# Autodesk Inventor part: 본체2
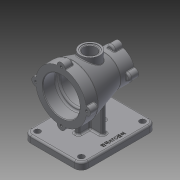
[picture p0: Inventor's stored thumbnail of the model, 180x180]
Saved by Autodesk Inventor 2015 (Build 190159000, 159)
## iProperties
Created: 2020-12
Part Number: 본체2
Material: 일반
Document SubType Name: Modeling
Designer: Lineart
Density: 1 g/cm^3
Appearance: 기본값
Author: Lineart
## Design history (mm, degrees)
sketch "스케치1"
  geometry: L1 (-50, 0)-(50, 0); L2 (-50, 0)-(-50, 44); L3 (-50, 44)-(-30, 44); L4 (-30, 44)-(25.698, 27.5); L5 (25.698, 27.5)-(50, 27.5); L6 (50, 27.5)-(50, 0); 2 further points
  constraints: 12 end point, 2 perpendicular, 1 coincident, 1 horizontal, 1 midpoint, 1 parallel, 1 vertical
  dimensions: "d1" = 88 diameter of L3 L1; "d2" = 55 diameter of L5 L1; "d4" = 100 distance between parallel lines of L6 L2; "d5" = 20 distance from line of L3.end L2; "d6" = 55.69798 horizontal distance of L3.end L4.end
revolve "회전1" sketch "스케치1" stored, may be unused: angle "d7" = 90 deg
node "작업 평면1"
node "작업 평면2"
sketch "스케치3"
  geometry: L1 (-65, -50)-(65, -50); L2 (65, -50)-(65, 50); L3 (65, 50)-(-65, 50); L4 (-65, 50)-(-65, -50); L5 (-65, -50)-(65, 50); L6 (65, -50)-(-65, 50); 1 further point
  constraints: 12 end point, 2 midpoint, 2 parallel, 1 horizontal, 1 perpendicular
  dimensions: "d9" = 130 distance of L3.end L2.end; "d10" = 100 distance of L2.end L1.end
extrude "돌출1" join sketch "스케치3" distance "d11" = 12; taper "d12" = 0 deg
sketch "스케치5"
  geometry: L1 (0, -4)-(0, 4); L2 (24, 0)-(-24, 0); L3 (-65, -50)-(-65, 50) reference; L4 (65, -50)-(-65, -50) reference; L5 (24, -4)-(24, 4); L6 (-24, -4)-(-24, 4); L7 (24, -4)-(-24, -4); L8 (24, 4)-(-24, 4); 1 further point
  constraints: 12 end point, 4 midpoint, 4 parallel
  dimensions: "d15" = 65 distance between parallel lines of L3 L1; "d16" = 50 distance between parallel lines of L2 L4; "d17" = 24 distance between parallel lines of L1 L5; "d18" = 24 distance between parallel lines of L1 L6; "d19" = 4 distance between parallel lines of L2 L7; "d20" = 4 distance between parallel lines of L2 L8
extrude "돌출2" join sketch "스케치5" distance "d21" = 67.5; taper "d22" = 0 deg
node "작업 평면4"
sketch "스케치6"
  geometry: L1 (-62.176, 4)-(12, 4); L2 (-62.176, -21)-(12, -21); L3 (-62.176, 29)-(12, 29); L4 (12, -46)-(12, 54) reference; L5 (-62.176, -21)-(-62.176, 29); L6 (12, -21)-(12, 29); 1 further point
  constraints: 10 end point, 2 midpoint, 2 parallel, 2 point on line, 1 collinear, 1 horizontal, 1 vertical
  dimensions: "d23" = 25 distance between parallel lines of L1 L2; "d24" = 25 distance between parallel lines of L1 L3; "d25" = 50 distance of L3.end L2.end (derived); "d26" = 74.17552 distance between parallel lines of L4 L5; "d27" = 25 distance from line of L4.end L3
extrude "돌출3" join sketch "스케치6" stored distance "d28" = 8; taper "d29" = 0 deg
sketch "스케치7"
  geometry: L1 (50, 0)-(-50, 0); L2 (50, 44)-(50, -44) reference; L3 (50, 0)-(50, -32); L4 (50, -32)-(30, -32); L5 (27, -29)-(27, -29); L6 (24, -26)-(-17, -26); L7 (-20, -23)-(-20, -23); L8 (-50, 27.5)-(-50, -27.5) reference; L9 (-23, -20)-(-50, -20); L10 (-50, -20)-(-50, 0); A1 r 3 centre (30, -29) between (27, -29) and (30, -32); A2 r 3 centre (24, -29) between (27, -29) and (24, -26); A3 r 3 centre (-17, -23) between (-20, -23) and (-17, -26); A4 r 3 centre (-23, -23) between (-20, -23) and (-23, -20); 1 further point
  constraints: 16 end point, 8 point on circle, 8 tangent, 4 centre point, 4 perpendicular, 3 equal radius, 2 horizontal, 2 midpoint, 2 point on line
  dimensions: "d30" = 64 diameter of L4 L1; "d31" = 52 diameter of L6 L1; "d33" = 23 distance between parallel lines of L5 L2; "d34" = 47 distance between parallel lines of L7 L5; "d36" = 40 diameter of L9 L1; "d37" = 30 distance between parallel lines of L8 L7 (derived); "d38" = 3 radius of A1
revolve "회전2" sketch "스케치7" stored, may be unused: angle "d39" = 90 deg
sketch "스케치8"
  geometry: C1 r 7 at (-44, 0); C2 r 7 at (0, -44); C3 r 7 at (44, 0); C4 r 7 at (0, 44); A1 r 44 centre (0, 0) between (-44, 0) and (0, 44) reference; 3 further points
  constraints: 4 centre point, 4 coincident, 4 point on circle, 2 horizontal alignment, 2 vertical alignment
  dimensions: "d40" = 7 radius of C1; "d41" = 7 radius of C2; "d42" = 7 radius of C3; "d45" = 7 radius of C4
extrude "돌출4" join sketch "스케치8" distance "d46" = 15; taper "d47" = 0 deg
sketch "스케치9"
  geometry: C1 r 7 at (27.5, 0); C2 r 7 at (0, 27.5); C3 r 7 at (-27.5, 0); C4 r 7 at (0, -27.5); A1 r 27.5 centre (0, 0) between (27.5, 0) and (0, 27.5) reference; A2 r 27.5 centre (0, 0) between (27.5, 0) and (0, 27.5) reference; 3 further points
  constraints: 8 point on circle, 4 centre point, 4 coincident, 2 horizontal alignment, 2 vertical alignment
  dimensions: "d48" = 7 radius of C1; "d49" = 7 radius of C2; "d50" = 7 radius of C3; "d51" = 7 radius of C4
extrude "돌출5" join sketch "스케치9" distance "d52" = 15; taper "d53" = 0 deg
hole "구멍1" diameter "d56" = 4.134; stored, may be unused: countersink angle "d60" = 90 deg, drill point angle "d62" = 118 deg; dims "d54" = 10, "d55" = 10, "d57" = 9, "d58" = 4, "d59" = 2, "d61" = 11
hole "구멍2" diameter "d65" = 4.134; stored, may be unused: countersink angle "d69" = 90 deg, drill point angle "d71" = 118 deg; dims "d63" = 10, "d64" = 10, "d66" = 9, "d67" = 4, "d68" = 2, "d70" = 11
hole "구멍3" diameter "d74" = 4.134; stored, may be unused: countersink angle "d78" = 90 deg, drill point angle "d80" = 118 deg; dims "d72" = 10, "d73" = 10, "d75" = 9, "d76" = 4, "d77" = 2, "d79" = 11
hole "구멍4" diameter "d83" = 4.134; stored, may be unused: countersink angle "d87" = 90 deg, drill point angle "d89" = 118 deg; dims "d81" = 10, "d82" = 10, "d84" = 9, "d85" = 4, "d86" = 2, "d88" = 11
hole "구멍5" diameter "d92" = 4.134; stored, may be unused: countersink angle "d96" = 90 deg, drill point angle "d98" = 118 deg; dims "d90" = 10, "d91" = 10, "d93" = 9, "d94" = 4, "d95" = 2, "d97" = 11
hole "구멍6" diameter "d101" = 4.134; stored, may be unused: countersink angle "d105" = 90 deg, drill point angle "d107" = 118 deg; dims "d99" = 10, "d100" = 10, "d102" = 9, "d103" = 4, "d104" = 2, "d106" = 11
hole "구멍7" diameter "d110" = 4.134; stored, may be unused: countersink angle "d114" = 90 deg, drill point angle "d116" = 118 deg; dims "d108" = 10, "d109" = 10, "d111" = 9, "d112" = 4, "d113" = 2, "d115" = 11
hole "구멍8" diameter "d119" = 4.134; stored, may be unused: countersink angle "d123" = 90 deg, drill point angle "d125" = 118 deg; dims "d117" = 10, "d118" = 10, "d120" = 9, "d121" = 4, "d122" = 2, "d124" = 11
fillet "모깎기1" dims "d126" = 12
fillet "모깎기2" dims "d127" = 3
sketch "스케치11"
  geometry: C1 r 5 at (53, -38); C2 r 5 at (53, 38); C3 r 5 at (-53, 38); C4 r 5 at (-53, -38); A1 r 12 centre (53, -38) between (53, -50) and (65, -38) reference; A2 r 12 centre (53, 38) between (65, 38) and (53, 50) reference; A3 r 12 centre (-53, 38) between (-53, 50) and (-65, 38) reference; A4 r 12 centre (-53, -38) between (-65, -38) and (-53, -50) reference; 1 further point
  constraints: 4 centre point, 4 coincident
  dimensions: "d128" = 10 diameter of C1; "d129" = 10 diameter of C2; "d130" = 10 diameter of C3; "d131" = 10 diameter of C4
extrude "돌출6" cut sketch "스케치11" stored distance "d132" = 15; taper "d133" = 0 deg
fillet "모깎기3" dims "d134" = 3
fillet "모깎기4" dims "d135" = 3
fillet "모깎기5" dims "d136" = 3
fillet "모깎기6" dims "d137" = 3
node "작업 평면5"
sketch "스케치13"
  geometry: C1 r 17 at (0, 0); 1 further point
  constraints: 1 centre point, 1 coincident
  dimensions: "d139" = 34 diameter of C1
extrude "돌출7" join sketch "스케치13" distance "d140" = 18.25; taper "d141" = 0 deg
sketch "스케치14"
  geometry: C1 r 14 at (0, 0); 1 further point
  constraints: 1 centre point, 1 coincident
  dimensions: "d142" = 28 diameter of C1
extrude "돌출8" cut sketch "스케치14" distance "d143" = 1; taper "d144" = 0 deg
sketch "스케치15"
  geometry: C1 r 11 at (0, 0); 1 further point
  constraints: 1 centre point, 1 coincident
  dimensions: "d145" = 22 diameter of C1
extrude "돌출9" cut sketch "스케치15" distance "d146" = 36; taper "d147" = 0 deg
fillet "모깎기7" dims "d148" = 3
fillet "모깎기8" dims "d149" = 1
fillet "모깎기9" dims "d150" = 1
chamfer "모따기1" distance "d151" = 1; stored, may be unused: second distance "d152" = 2, angle "d153" = 45 deg
fillet "모깎기10" dims "d154" = 1
sketch "스케치16"
  geometry: L1 (53, 50)-(-53, 50) reference; 2 further points
  constraints: 1 vertical alignment, 1 other
  dimensions: "d155" = 10 vertical distance of L1.start point (0, 40)
feature "엠보싱1" sketch "스케치16" dims "d12" = 0, "d156" = 0.5, "d157" = 0
node "솔리드1"
